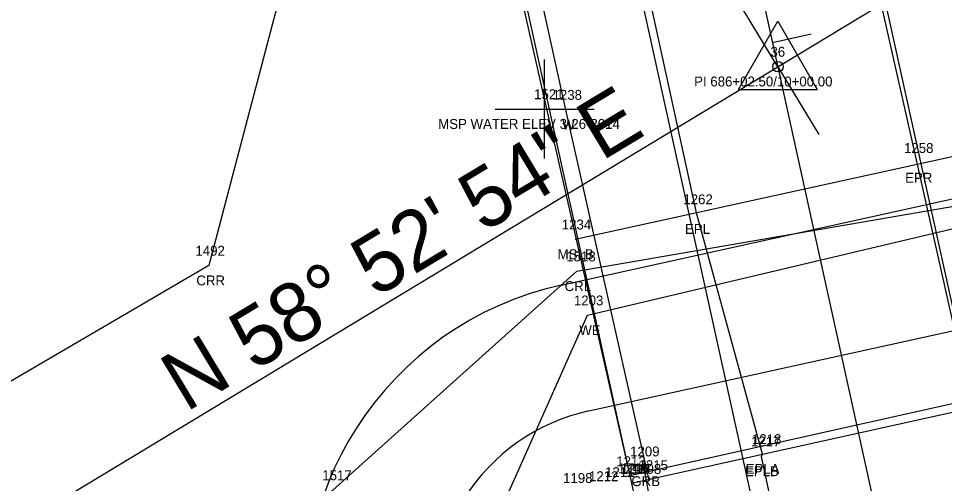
# Model space of a CAD drawing. Extents: x 2521558 to 2524785, y 882711 to 887632.
# Drawn here: x 2523713 to 2523806.5, y 885077.6 to 885124.5 of the extents above; entities that cross this region are included whole.
import ezdxf

# ---------------------------------------------------------------- set-up
doc = ezdxf.new("R2010")
doc.units = 0
for name, color, linetype in [('RD_EX_BldgApp', 7, 'Continuous'), ('RD_EX_BldgApp_txCode', 7, 'Continuous'), ('RD_EX_Bridge', 7, 'Continuous'), ('RD_EX_Bridge_txCode', 7, 'Continuous'), ('RD_EX_Conc_txCode', 7, 'Continuous'), ('RD_EX_GuardRail', 7, 'Continuous'), ('RD_EX_GuardRail_txCode', 7, 'Continuous'), ('RD_EX_H2O', 7, 'Continuous'), ('RD_EX_H2O_txCode', 7, 'Continuous'), ('RD_EX_Misc', 7, 'Continuous'), ('RD_EX_Misc_txCode', 7, 'Continuous'), ('RD_EX_Road', 7, 'Continuous'), ('RD_EX_Road_txCode', 7, 'Continuous'), ('RD_EX_VEG_txCode', 7, 'Continuous'), ('RD_HC_Cl', 7, 'Continuous'), ('RD_HC_Data', 7, 'Continuous'), ('RD_HC_Data_Tic', 7, 'Continuous'), ('RD_HC_txCode', 7, 'Continuous'), ('RD_PD_Bridge', 7, 'Continuous'), ('RD_PD_CstnLmt', 7, 'Continuous'), ('RD_PD_DR_ErosCtrl', 7, 'Continuous'), ('RD_PD_Final_TrvlWay', 7, 'Continuous'), ('RD_SMD_Locator', 7, 'Continuous')]:
    doc.layers.add(name, color=color, linetype=linetype)

msp = doc.modelspace()

# ---------------------------------------------------------------- linework, layer by layer
at = {"layer": 'RD_EX_BldgApp'}
msp.add_lwpolyline([(2523776.677, 885077.915), (2523768.273, 885115.309), (2523760.204, 885151.895)], dxfattribs=at)
at = {"layer": 'RD_EX_Bridge'}
msp.add_lwpolyline([(2523774.906, 885077.596), (2523821.197, 885087.829), (2523805.064, 885161.895), (2523758.145, 885151.437), (2523774.906, 885077.596)], dxfattribs=at)
at = {"layer": 'RD_EX_GuardRail'}
msp.add_lwpolyline([(2523787.377, 885001.584), (2523782.908, 885042.685), (2523776.151, 885079.302)], dxfattribs=at)
at = {"layer": 'RD_EX_H2O'}
for points in [[(2523582.816, 884766.342), (2523598.112, 884856.984), (2523627.586, 884901.753), (2523623.762, 884928.278), (2523586.58, 884955.428), (2523600.942, 884974.118), (2523633.055, 884997.681), (2523679.166, 885037.048), (2523744.717, 885076.895), (2523769.376, 885098.995), (2523825.47, 885108.66), (2523825.47, 885108.66), (2523845.237, 885110.828), (2523890.252, 885154.934), (2523858.435, 885178.041), (2523850.814, 885196.928), (2523892.509, 885249.744), (2523936.89, 885290.086), (2523980.857, 885285.467), (2524009.058, 885269.77), (2524037.386, 885280.087)], [(2523741.751, 885135.924), (2523732.183, 885099.571), (2523664.897, 885060.261), (2523614.863, 885022.018), (2523558.95, 884972.63), (2523560.622, 884942.416), (2523490.005, 884911.763)], [(2523792.732, 884941.121), (2523763.674, 885051.555), (2523756.264, 885062.719), (2523770.471, 885094.548), (2523817.567, 885105.706), (2523827.825, 885105.996)]]:
    msp.add_lwpolyline(points, dxfattribs=at)
at = {"layer": 'RD_EX_Misc'}
for p, q in [((2523766.128, 885110.375), (2523766.128, 885120.375)), ((2523761.128, 885115.375), (2523771.128, 885115.375)), ((2523816.084, 885112.468), (2523769.205, 885102.217)), ((2523774.429, 885078.307), (2523821.346, 885088.784))]:
    msp.add_line(p, q, dxfattribs=at)
at = {"layer": 'RD_EX_Road'}
for p, q in [((2523803.791, 885109.941), (2523798.302, 885134.145)), ((2523781.516, 885104.768), (2523776.178, 885129.21)), ((2523809.315, 885085.19), (2523803.791, 885109.941)), ((2523788.138, 885080.544), (2523781.516, 885104.768)), ((2523788.047, 885080.306), (2523788.138, 885080.544)), ((2523795.465, 885045.906), (2523788.047, 885080.306))]:
    msp.add_line(p, q, dxfattribs=at)
at = {"layer": 'RD_HC_Cl'}
for p, q in [((2523641.165, 885794.201), (2524197.759, 883266.557)), ((2523672.044, 885048.634), (2523837.18, 885148.323))]:
    msp.add_line(p, q, dxfattribs=at)
at = {"layer": 'RD_HC_Data'}
for p, q in [((2523785.73, 885117.368), (2523789.702, 885124.248)), ((2523789.702, 885124.248), (2523793.671, 885117.368)), ((2523785.73, 885117.368), (2523793.671, 885117.368))]:
    msp.add_line(p, q, dxfattribs=at)
msp.add_circle((2523789.701, 885119.661), 0.529, dxfattribs=at)
at = {"layer": 'RD_HC_Data_Tic'}
for p, q in [((2523789.692, 885119.656), (2523785.558, 885126.504)), ((2523789.164, 885122.1), (2523793.07, 885122.96)), ((2523789.692, 885119.656), (2523793.827, 885112.807))]:
    msp.add_line(p, q, dxfattribs=at)
at = {"layer": 'RD_PD_Bridge'}
msp.add_lwpolyline([(2523752.772, 885178.086), (2523780.729, 885051.128)], dxfattribs=at)
at = {"layer": 'RD_PD_CstnLmt'}
msp.add_lwpolyline([(2523770.593, 885084.896), (2523821.135, 885096.025)], dxfattribs=at)
msp.add_arc((2523774.894, 885065.364), 20, 102.41848, 192.06773, dxfattribs=at)
at = {"layer": 'RD_PD_DR_ErosCtrl'}
msp.add_lwpolyline([(2523767.797, 885097.592), (2523818.34, 885108.721)], dxfattribs=at)
msp.add_arc((2523774.894, 885065.364), 33, 102.41848, 192.06773, dxfattribs=at)
at = {"layer": 'RD_PD_Final_TrvlWay'}
for p, q in [((2523741.744, 885393.246), (2524015.933, 884148.078)), ((2523718.306, 885388.085), (2523992.495, 884142.916))]:
    msp.add_line(p, q, dxfattribs=at)
at = {"layer": 'RD_SMD_Locator'}
for centre in [(2523789.701, 885119.661), (2523768.273, 885115.309), (2523803.791, 885109.941), (2523781.516, 885104.768), (2523769.205, 885102.217), (2523732.183, 885099.571), (2523769.376, 885098.995), (2523770.471, 885094.548), (2523788.138, 885080.544), (2523788.047, 885080.306), (2523776.151, 885079.302), (2523774.429, 885078.307), (2523776.677, 885077.915), (2523774.906, 885077.596), (2523774.906, 885077.596)]:
    msp.add_circle(centre, 0.001, dxfattribs=at)

# ---------------------------------------------------------------- texts
at = {"layer": 'RD_EX_BldgApp_txCode'}
for s, p in [('1238', (2523766.926, 885116.309)), ('W', (2523767.903, 885113.309)), ('1215', (2523775.614, 885078.915))]:
    msp.add_text(s, height=1, dxfattribs=at).set_placement(p)
at = {"layer": 'RD_EX_Bridge_txCode'}
for s, p in [('1246', (2523773.536, 885078.596)), ('1210', (2523773.795, 885078.54)), ('1214', (2523773.843, 885078.596)), ('1212', (2523770.605, 885077.8)), ('1211', (2523772.238, 885078.212))]:
    msp.add_text(s, height=1, dxfattribs=at).set_placement(p)
at = {"layer": 'RD_EX_Conc_txCode'}
msp.add_text('1208', height=1, dxfattribs=at).set_placement((2523774.937, 885078.543))
at = {"layer": 'RD_EX_GuardRail_txCode'}
for s, p in [('1209', (2523774.765, 885080.302)), ('GRB', (2523774.899, 885077.302))]:
    msp.add_text(s, height=1, dxfattribs=at).set_placement(p)
at = {"layer": 'RD_EX_H2O_txCode'}
for s, p in [('1492', (2523730.836, 885100.571)), ('1518', (2523768.313, 885099.995)), ('CRR', (2523730.931, 885097.571)), ('CRL', (2523768.148, 885096.995)), ('1203', (2523769.085, 885095.548)), ('WE', (2523769.632, 885092.548)), ('1517', (2523743.655, 885077.895))]:
    msp.add_text(s, height=1, dxfattribs=at).set_placement(p)
at = {"layer": 'RD_EX_Misc_txCode'}
for s, p in [('1521', (2523765.065, 885116.375)), ('MSP WATER ELEV 3-26-2014', (2523755.372, 885113.375)), ('1234', (2523767.858, 885103.217)), ('MSLB', (2523767.441, 885100.217)), ('1213', (2523773.366, 885079.307))]:
    msp.add_text(s, height=1, dxfattribs=at).set_placement(p)
at = {"layer": 'RD_EX_Road_txCode'}
for s, p in [('1258', (2523802.445, 885110.941)), ('EPR', (2523802.563, 885107.941)), ('1262', (2523780.146, 885105.768)), ('EPL', (2523780.311, 885102.768)), ('1217', (2523786.984, 885081.306)), ('1218', (2523787.075, 885081.544)), ('EPLA', (2523786.445, 885078.544)), ('EPLB', (2523786.37, 885078.306))]:
    msp.add_text(s, height=1, dxfattribs=at).set_placement(p)
at = {"layer": 'RD_EX_VEG_txCode'}
msp.add_text('1198', height=1, dxfattribs=at).set_placement((2523767.993, 885077.621))
at = {"layer": 'RD_HC_Data'}
msp.add_text('N 58%%d 52\' 54" E', height=6, rotation=31.1184, dxfattribs=at).set_placement((2523729.873, 885084.712))
at = {"layer": 'RD_HC_txCode'}
for s, p in [('36', (2523788.945, 885120.661)), ('PI 686+02.50/10+00.00', (2523781.236, 885117.661))]:
    msp.add_text(s, height=1, dxfattribs=at).set_placement(p)

doc.saveas('drawing.dxf')
